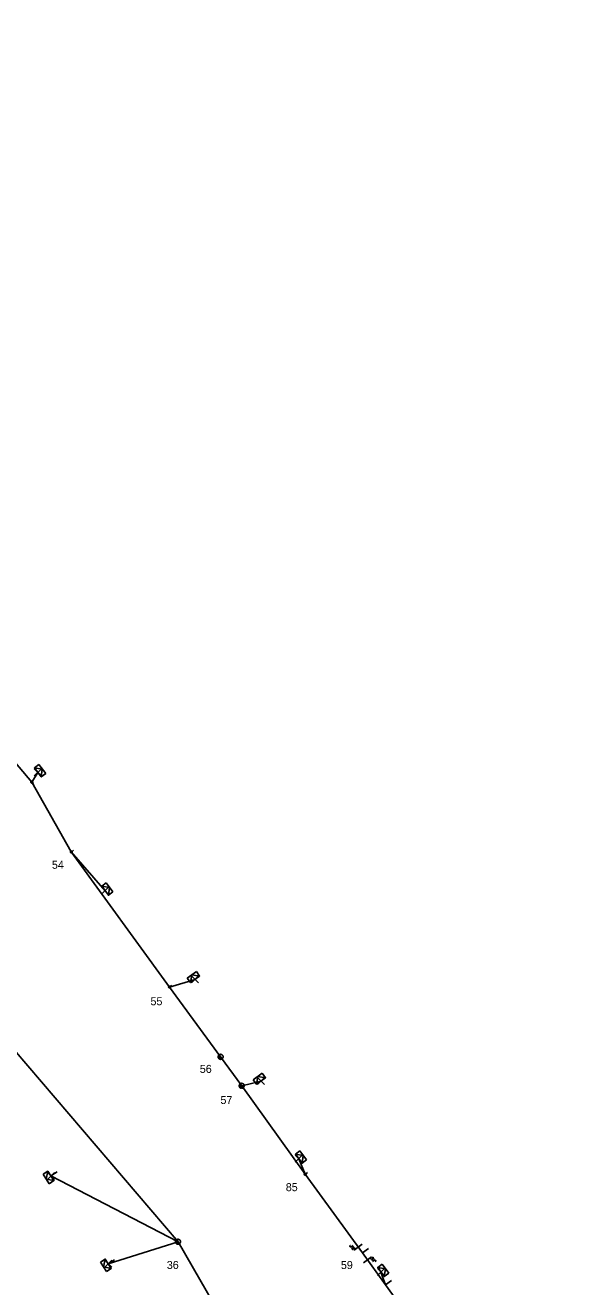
# Model space of a CAD drawing. Extents: x -536149 to -535465, y -1201639 to -1201298.
# Drawn here: x -535608.3 to -535540.4, y -1201493.4 to -1201335.8 of the extents above; entities that cross this region are included whole.
import ezdxf

# ---------------------------------------------------------------- set-up
doc = ezdxf.new("R2010")
doc.units = 0
for name, color, linetype in [('Vrstva 1', 7, 'Continuous'), ('Vrstva 13', 7, 'Continuous'), ('Vrstva 14', 7, 'Continuous'), ('Vrstva 15', 7, 'Continuous'), ('Vrstva 18', 7, 'Continuous'), ('Vrstva 2', 7, 'Continuous'), ('Vrstva 31', 7, 'Continuous'), ('Vrstva 34', 7, 'Continuous'), ('Vrstva 4', 7, 'Continuous'), ('Vrstva 50', 7, 'Continuous'), ('Vrstva 54', 7, 'Continuous'), ('Vrstva 9', 7, 'Continuous')]:
    doc.layers.add(name, color=color, linetype=linetype)

# ---------------------------------------------------------------- blocks, each defined once
blk = doc.blocks.new('NN440')
at = {"layer": 'Vrstva 2'}
for points in [[(0.63, 0), (0.63, 0.06), (0.62, 0.13), (0.6, 0.19), (0.58, 0.25), (0.55, 0.31), (0.51, 0.37), (0.47, 0.42), (0.42, 0.46), (0.37, 0.51), (0.32, 0.54), (0.26, 0.57), (0.2, 0.59), (0.13, 0.61), (0.07, 0.62), (0, 0.63), (-0.06, 0.62), (-0.13, 0.61), (-0.19, 0.59), (-0.26, 0.57), (-0.31, 0.54), (-0.37, 0.51), (-0.42, 0.46), (-0.47, 0.42), (-0.51, 0.37), (-0.54, 0.31), (-0.57, 0.25), (-0.6, 0.19), (-0.62, 0.13), (-0.63, 0.06), (-0.63, 0), (-0.63, -0.07), (-0.62, -0.14), (-0.6, -0.2), (-0.57, -0.26), (-0.54, -0.32), (-0.51, -0.37), (-0.47, -0.43), (-0.42, -0.47), (-0.37, -0.51), (-0.31, -0.55), (-0.26, -0.58), (-0.19, -0.6), (-0.13, -0.62), (-0.06, -0.63), (0, -0.63), (0.07, -0.63), (0.13, -0.62), (0.2, -0.6), (0.26, -0.58), (0.32, -0.55), (0.37, -0.51), (0.42, -0.47), (0.47, -0.43), (0.51, -0.37), (0.55, -0.32), (0.58, -0.26), (0.6, -0.2), (0.62, -0.14), (0.63, -0.07), (0.63, 0)], [(-0.63, 0), (0.63, 0)], [(-0.6, -0.18), (0.57, -0.18)], [(-0.51, -0.32), (0.5, -0.32)], [(-0.37, -0.47), (0.35, -0.47)]]:
    blk.add_lwpolyline(points, dxfattribs=at)
blk = doc.blocks.new('NN840')
at = {"layer": 'Vrstva 15'}
for points in [[(0, 0.62), (0, -0.63)], [(-0.75, -0.71), (-0.75, -0.66)], [(-0.73, -0.76), (-0.75, -0.71)], [(-0.66, -0.8), (-0.73, -0.76)], [(-0.63, -0.8), (-0.66, -0.8)], [(-0.56, -0.76), (-0.63, -0.8)], [(-0.54, -0.71), (-0.56, -0.76)], [(-0.54, -0.38), (-0.54, -0.71)], [(-0.33, -0.38), (-0.33, -0.8)], [(-0.33, -0.64), (-0.13, -0.38)], [(-0.26, -0.56), (-0.09, -0.8)]]:
    blk.add_lwpolyline(points, dxfattribs=at)
blk = doc.blocks.new('NN800')
at = {"layer": 'Vrstva 1'}
for points in [[(-0.44, 0.44), (0.44, -0.44)], [(-0.44, -0.44), (0.44, 0.44)]]:
    blk.add_lwpolyline(points, dxfattribs=at)
blk = doc.blocks.new('NN630')
at = {"layer": 'Vrstva 9'}
for points in [[(0, -0.7), (-0.7, 0)], [(-0.7, -0.7), (-0.7, 0), (0.7, 0), (0.7, -0.7)], [(-0.7, -0.7), (0.7, -0.7)], [(0, -0.7), (0.7, 0)]]:
    blk.add_lwpolyline(points, dxfattribs=at)
blk = doc.blocks.new('NN500')
at = {"layer": 'Vrstva 2'}
for points in [[(0, -0.24), (0.02, -0.23), (0.05, -0.23), (0.07, -0.22), (0.09, -0.22), (0.12, -0.2), (0.14, -0.19), (0.16, -0.18), (0.17, -0.16), (0.19, -0.14), (0.2, -0.12), (0.21, -0.1), (0.22, -0.07), (0.23, -0.05), (0.23, -0.02), (0.23, 0), (0.23, 0.02), (0.23, 0.05), (0.22, 0.07), (0.21, 0.1), (0.2, 0.12), (0.19, 0.14), (0.17, 0.16), (0.16, 0.17), (0.14, 0.19), (0.12, 0.2), (0.09, 0.21), (0.07, 0.22), (0.05, 0.23), (0.02, 0.23), (0, 0.23), (-0.03, 0.23), (-0.05, 0.23), (-0.07, 0.22), (-0.1, 0.21), (-0.12, 0.2), (-0.14, 0.19), (-0.16, 0.17), (-0.18, 0.16), (-0.19, 0.14), (-0.2, 0.12), (-0.22, 0.1), (-0.22, 0.07), (-0.23, 0.05), (-0.23, 0.02), (-0.24, 0), (-0.23, -0.02), (-0.23, -0.05), (-0.22, -0.07), (-0.22, -0.1), (-0.2, -0.12), (-0.19, -0.14), (-0.18, -0.16), (-0.16, -0.18), (-0.14, -0.19), (-0.12, -0.2), (-0.1, -0.22), (-0.07, -0.22), (-0.05, -0.23), (-0.03, -0.23), (0, -0.24)], [(0, -0.24), (0.02, -0.23), (0.05, -0.23), (0.07, -0.22), (0.09, -0.22), (0.12, -0.2), (0.14, -0.19), (0.16, -0.18), (0.17, -0.16), (0.19, -0.14), (0.2, -0.12), (0.21, -0.1), (0.22, -0.07), (0.23, -0.05), (0.23, -0.02), (0.23, 0), (0.23, 0.02), (0.23, 0.05), (0.22, 0.07), (0.21, 0.1), (0.2, 0.12), (0.19, 0.14), (0.17, 0.16), (0.16, 0.17), (0.14, 0.19), (0.12, 0.2), (0.09, 0.21), (0.07, 0.22), (0.05, 0.23), (0.02, 0.23), (0, 0.23), (-0.03, 0.23), (-0.05, 0.23), (-0.07, 0.22), (-0.1, 0.21), (-0.12, 0.2), (-0.14, 0.19), (-0.16, 0.17), (-0.18, 0.16), (-0.19, 0.14), (-0.2, 0.12), (-0.22, 0.1), (-0.22, 0.07), (-0.23, 0.05), (-0.23, 0.02), (-0.24, 0), (-0.23, -0.02), (-0.23, -0.05), (-0.22, -0.07), (-0.22, -0.1), (-0.2, -0.12), (-0.19, -0.14), (-0.18, -0.16), (-0.16, -0.18), (-0.14, -0.19), (-0.12, -0.2), (-0.1, -0.22), (-0.07, -0.22), (-0.05, -0.23), (-0.03, -0.23), (0, -0.24)], [(0, -0.21), (0.02, -0.2), (0.04, -0.2), (0.06, -0.2), (0.08, -0.19), (0.1, -0.18), (0.12, -0.17), (0.14, -0.15), (0.15, -0.14), (0.16, -0.12), (0.18, -0.1), (0.19, -0.08), (0.19, -0.06), (0.2, -0.04), (0.2, -0.02), (0.2, 0), (0.2, 0.02), (0.2, 0.04), (0.19, 0.06), (0.19, 0.08), (0.18, 0.1), (0.16, 0.12), (0.15, 0.14), (0.14, 0.15), (0.12, 0.17), (0.1, 0.18), (0.08, 0.19), (0.06, 0.19), (0.04, 0.2), (0.02, 0.2), (0, 0.2), (-0.02, 0.2), (-0.04, 0.2), (-0.06, 0.19), (-0.08, 0.19), (-0.1, 0.18), (-0.12, 0.17), (-0.14, 0.15), (-0.15, 0.14), (-0.17, 0.12), (-0.18, 0.1), (-0.19, 0.08), (-0.2, 0.06), (-0.2, 0.04), (-0.21, 0.02), (-0.21, 0), (-0.21, -0.02), (-0.2, -0.04), (-0.2, -0.06), (-0.19, -0.08), (-0.18, -0.1), (-0.17, -0.12), (-0.15, -0.14), (-0.14, -0.15), (-0.12, -0.17), (-0.1, -0.18), (-0.08, -0.19), (-0.06, -0.2), (-0.04, -0.2), (-0.02, -0.2), (0, -0.21)], [(0, -0.18), (0.02, -0.18), (0.04, -0.17), (0.05, -0.17), (0.07, -0.16), (0.09, -0.15), (0.1, -0.14), (0.12, -0.13), (0.13, -0.12), (0.14, -0.1), (0.15, -0.09), (0.16, -0.07), (0.17, -0.05), (0.17, -0.04), (0.17, -0.02), (0.17, 0), (0.17, 0.02), (0.17, 0.04), (0.17, 0.05), (0.16, 0.07), (0.15, 0.09), (0.14, 0.1), (0.13, 0.12), (0.12, 0.13), (0.1, 0.14), (0.09, 0.15), (0.07, 0.16), (0.05, 0.17), (0.04, 0.17), (0.02, 0.17), (0, 0.18), (-0.02, 0.17), (-0.04, 0.17), (-0.06, 0.17), (-0.07, 0.16), (-0.09, 0.15), (-0.1, 0.14), (-0.12, 0.13), (-0.13, 0.12), (-0.14, 0.1), (-0.15, 0.09), (-0.16, 0.07), (-0.17, 0.05), (-0.17, 0.04), (-0.18, 0.02), (-0.18, 0), (-0.18, -0.02), (-0.17, -0.04), (-0.17, -0.05), (-0.16, -0.07), (-0.15, -0.09), (-0.14, -0.1), (-0.13, -0.12), (-0.12, -0.13), (-0.1, -0.14), (-0.09, -0.15), (-0.07, -0.16), (-0.06, -0.17), (-0.04, -0.17), (-0.02, -0.18), (0, -0.18)], [(0, -0.15), (0.01, -0.15), (0.03, -0.14), (0.04, -0.14), (0.06, -0.13), (0.07, -0.13), (0.08, -0.12), (0.1, -0.11), (0.11, -0.1), (0.12, -0.09), (0.13, -0.07), (0.13, -0.06), (0.14, -0.05), (0.14, -0.03), (0.14, -0.02), (0.14, 0), (0.14, 0.01), (0.14, 0.03), (0.14, 0.04), (0.13, 0.06), (0.13, 0.07), (0.12, 0.09), (0.11, 0.1), (0.1, 0.11), (0.08, 0.12), (0.07, 0.13), (0.06, 0.13), (0.04, 0.14), (0.03, 0.14), (0.01, 0.14), (0, 0.15), (-0.02, 0.14), (-0.03, 0.14), (-0.05, 0.14), (-0.06, 0.13), (-0.07, 0.13), (-0.09, 0.12), (-0.1, 0.11), (-0.11, 0.1), (-0.12, 0.09), (-0.13, 0.07), (-0.13, 0.06), (-0.14, 0.04), (-0.14, 0.03), (-0.15, 0.01), (-0.15, 0), (-0.15, -0.02), (-0.14, -0.03), (-0.14, -0.05), (-0.13, -0.06), (-0.13, -0.07), (-0.12, -0.09), (-0.11, -0.1), (-0.1, -0.11), (-0.09, -0.12), (-0.07, -0.13), (-0.06, -0.13), (-0.05, -0.14), (-0.03, -0.14), (-0.02, -0.15), (0, -0.15)], [(0, -0.12), (0.01, -0.12), (0.02, -0.11), (0.03, -0.11), (0.05, -0.11), (0.06, -0.1), (0.07, -0.09), (0.08, -0.09), (0.09, -0.08), (0.09, -0.07), (0.1, -0.06), (0.11, -0.05), (0.11, -0.04), (0.11, -0.02), (0.11, -0.01), (0.12, 0), (0.11, 0.01), (0.11, 0.02), (0.11, 0.04), (0.11, 0.05), (0.1, 0.06), (0.09, 0.07), (0.09, 0.08), (0.08, 0.09), (0.07, 0.09), (0.06, 0.1), (0.05, 0.11), (0.03, 0.11), (0.02, 0.11), (0.01, 0.12), (0, 0.12), (-0.01, 0.12), (-0.03, 0.11), (-0.04, 0.11), (-0.05, 0.11), (-0.06, 0.1), (-0.07, 0.09), (-0.08, 0.09), (-0.09, 0.08), (-0.1, 0.07), (-0.1, 0.06), (-0.11, 0.05), (-0.11, 0.04), (-0.12, 0.02), (-0.12, 0.01), (-0.12, 0), (-0.12, -0.01), (-0.12, -0.02), (-0.11, -0.04), (-0.11, -0.05), (-0.1, -0.06), (-0.1, -0.07), (-0.09, -0.08), (-0.08, -0.09), (-0.07, -0.09), (-0.06, -0.1), (-0.05, -0.11), (-0.04, -0.11), (-0.03, -0.11), (-0.01, -0.12), (0, -0.12)], [(0, -0.09), (0.01, -0.09), (0.02, -0.09), (0.03, -0.08), (0.03, -0.08), (0.04, -0.08), (0.05, -0.07), (0.06, -0.07), (0.06, -0.06), (0.07, -0.05), (0.07, -0.04), (0.08, -0.04), (0.08, -0.03), (0.08, -0.02), (0.09, -0.01), (0.09, 0), (0.09, 0.01), (0.08, 0.02), (0.08, 0.03), (0.08, 0.03), (0.07, 0.04), (0.07, 0.05), (0.06, 0.06), (0.06, 0.06), (0.05, 0.07), (0.04, 0.07), (0.03, 0.08), (0.03, 0.08), (0.02, 0.08), (0.01, 0.09), (0, 0.09), (-0.01, 0.09), (-0.02, 0.08), (-0.03, 0.08), (-0.04, 0.08), (-0.04, 0.07), (-0.05, 0.07), (-0.06, 0.06), (-0.07, 0.06), (-0.07, 0.05), (-0.08, 0.04), (-0.08, 0.03), (-0.08, 0.03), (-0.09, 0.02), (-0.09, 0.01), (-0.09, 0), (-0.09, -0.01), (-0.09, -0.02), (-0.08, -0.03), (-0.08, -0.04), (-0.08, -0.04), (-0.07, -0.05), (-0.07, -0.06), (-0.06, -0.07), (-0.05, -0.07), (-0.04, -0.08), (-0.04, -0.08), (-0.03, -0.08), (-0.02, -0.09), (-0.01, -0.09), (0, -0.09)], [(0, -0.06), (0, -0.06), (0.01, -0.06), (0.02, -0.05), (0.02, -0.05), (0.03, -0.05), (0.03, -0.05), (0.04, -0.04), (0.04, -0.04), (0.05, -0.03), (0.05, -0.03), (0.05, -0.02), (0.05, -0.02), (0.05, -0.01), (0.06, -0.01), (0.06, 0), (0.06, 0.01), (0.05, 0.01), (0.05, 0.02), (0.05, 0.02), (0.05, 0.03), (0.05, 0.03), (0.04, 0.04), (0.04, 0.04), (0.03, 0.05), (0.03, 0.05), (0.02, 0.05), (0.02, 0.05), (0.01, 0.06), (0, 0.06), (0, 0.06), (-0.01, 0.06), (-0.01, 0.06), (-0.02, 0.05), (-0.02, 0.05), (-0.03, 0.05), (-0.03, 0.05), (-0.04, 0.04), (-0.04, 0.04), (-0.05, 0.03), (-0.05, 0.03), (-0.05, 0.02), (-0.06, 0.02), (-0.06, 0.01), (-0.06, 0.01), (-0.06, 0), (-0.06, -0.01), (-0.06, -0.01), (-0.06, -0.02), (-0.05, -0.02), (-0.05, -0.03), (-0.05, -0.03), (-0.04, -0.04), (-0.04, -0.04), (-0.03, -0.05), (-0.03, -0.05), (-0.02, -0.05), (-0.02, -0.05), (-0.01, -0.06), (-0.01, -0.06), (0, -0.06)], [(0, -0.03), (0, -0.03), (0, -0.03), (0.01, -0.03), (0.01, -0.03), (0.01, -0.02), (0.02, -0.02), (0.02, -0.02), (0.02, -0.02), (0.02, -0.02), (0.02, -0.01), (0.02, -0.01), (0.03, -0.01), (0.03, -0.01), (0.03, 0), (0.03, 0), (0.03, 0), (0.03, 0.01), (0.03, 0.01), (0.02, 0.01), (0.02, 0.01), (0.02, 0.02), (0.02, 0.02), (0.02, 0.02), (0.02, 0.02), (0.01, 0.02), (0.01, 0.02), (0.01, 0.03), (0, 0.03), (0, 0.03), (0, 0.03), (0, 0.03), (-0.01, 0.03), (-0.01, 0.03), (-0.01, 0.02), (-0.02, 0.02), (-0.02, 0.02), (-0.02, 0.02), (-0.02, 0.02), (-0.02, 0.02), (-0.03, 0.01), (-0.03, 0.01), (-0.03, 0.01), (-0.03, 0.01), (-0.03, 0), (-0.03, 0), (-0.03, 0), (-0.03, -0.01), (-0.03, -0.01), (-0.03, -0.01), (-0.03, -0.01), (-0.02, -0.02), (-0.02, -0.02), (-0.02, -0.02), (-0.02, -0.02), (-0.02, -0.02), (-0.01, -0.03), (-0.01, -0.03), (-0.01, -0.03), (0, -0.03), (0, -0.03)], [(0.23, 0), (0.7, 0)]]:
    blk.add_lwpolyline(points, dxfattribs=at)
blk = doc.blocks.new('NN510')
at = {"layer": 'Vrstva 2'}
blk.add_lwpolyline([(0, 0), (0, 0.94)], dxfattribs=at)

msp = doc.modelspace()

# ---------------------------------------------------------------- linework, layer by layer
at = {"layer": 'Vrstva 1'}
for points in [[(-535704.28, -1201335.78), (-535687.29, -1201370.27), (-535663.05, -1201399.63), (-535635.32, -1201433.41), (-535614.86, -1201457.77), (-535589.24, -1201487.74), (-535570.26, -1201520.7), (-535562.05, -1201543.24)], [(-535566.21, -1201489.13), (-535573.36, -1201479.31), (-535581.29, -1201468.26), (-535583.93, -1201464.64), (-535590.3, -1201455.92), (-535602.57, -1201439.04), (-535607.5, -1201430.34), (-535618.17, -1201417.76), (-535627.8, -1201404.56)]]:
    msp.add_lwpolyline(points, dxfattribs=at)
at = {"layer": 'Vrstva 4'}
msp.add_lwpolyline([(-535589.24, -1201487.74), (-535605.12, -1201479.52)], dxfattribs=at)
at = {"layer": 'Vrstva 50'}
msp.add_lwpolyline([(-535540.44, -1201538.36), (-535540.52, -1201538.12), (-535547.83, -1201515.44), (-535551.38, -1201509.64), (-535552.07, -1201508.68), (-535553.54, -1201506.64), (-535563.32, -1201493.12), (-535566.21, -1201489.13)], dxfattribs=at)
at = {"layer": 'Vrstva 54'}
for points in [[(-535607.5, -1201430.34), (-535606.75, -1201429.11)], [(-535602.57, -1201439.04), (-535598.35, -1201443.89)], [(-535590.3, -1201455.92), (-535587.11, -1201454.96)], [(-535581.29, -1201468.26), (-535578.87, -1201467.66)], [(-535573.36, -1201479.31), (-535574.16, -1201477.37)], [(-535589.24, -1201487.74), (-535597.96, -1201490.49)], [(-535563.32, -1201493.12), (-535563.89, -1201491.52)]]:
    msp.add_lwpolyline(points, dxfattribs=at)

# ---------------------------------------------------------------- block references
at = {"layer": 'Vrstva 13'}
for name, p, xscale, yscale, rotation in [('NN500', (-535607.5, -1201430.34), 0.49999999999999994, 0.5000000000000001, -53.199000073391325), ('NN500', (-535602.57, -1201439.05), 0.49999999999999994, 0.5000000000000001, 36.481000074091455), ('NN500', (-535590.3, -1201455.92), 0.49999999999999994, 0.5000000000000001, 36.481000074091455), ('NN440', (-535583.92, -1201464.64), 0.5, 0.5, -53.95204996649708), ('NN440', (-535581.29, -1201468.26), 0.5, 0.5, -53.95204988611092), ('NN500', (-535573.36, -1201479.31), 0.5, 0.5, 36.27199992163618), ('NN440', (-535589.24, -1201487.74), 0.5000000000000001, 0.4999999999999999, -60.05424448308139)]:
    msp.add_blockref(name, p, dxfattribs=dict(at, xscale=xscale, yscale=yscale, rotation=rotation))
for p, rotation in [((-535605.12, -1201479.52), -57.00316657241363), ((-535566.21, -1201489.13), -54.08653611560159), ((-535597.96, -1201490.49), -57.29474991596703), ((-535563.32, -1201493.12), -54.08520270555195)]:
    msp.add_blockref('NN510', p, dxfattribs=dict(at, rotation=rotation))
at = {"layer": 'Vrstva 18'}
for p, rotation in [((-535566.74, -1201488.41), -53.931013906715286), ((-535565.58, -1201490.01), 125.93150832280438)]:
    msp.add_blockref('NN840', p, dxfattribs=dict(at, rotation=rotation))
at = {"layer": 'Vrstva 31'}
for p, rotation in [((-535606.75, -1201429.11), 126.64183331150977), ((-535598.35, -1201443.89), 126.50239720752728), ((-535587.11, -1201454.96), -144.3667332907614), ((-535578.87, -1201467.66), -143.90412779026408), ((-535574.16, -1201477.37), 126.36712225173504), ((-535605.12, -1201479.52), -57.01241659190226), ((-535597.96, -1201490.49), -57.29356387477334), ((-535563.89, -1201491.52), 125.92456671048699)]:
    msp.add_blockref('NN630', p, dxfattribs=dict(at, rotation=rotation))
at = {"layer": 'Vrstva 34'}
for p in [(-535606.75, -1201429.11), (-535598.35, -1201443.89), (-535587.11, -1201454.96), (-535578.87, -1201467.66), (-535574.16, -1201477.37), (-535605.12, -1201479.52), (-535597.96, -1201490.49), (-535563.89, -1201491.52)]:
    msp.add_blockref('NN800', p, dxfattribs=at)

# ---------------------------------------------------------------- texts
at = {"layer": 'Vrstva 14'}
for s, p in [('54', (-535604.99, -1201441.15)), ('55', (-535592.68, -1201458.2)), ('56', (-535586.52, -1201466.65)), ('57', (-535583.94, -1201470.53)), ('85', (-535575.78, -1201481.42)), ('36', (-535590.64, -1201491.14)), ('59', (-535568.9, -1201491.15))]:
    msp.add_text(s, height=1, dxfattribs=at).set_placement(p)

doc.saveas('drawing.dxf')
